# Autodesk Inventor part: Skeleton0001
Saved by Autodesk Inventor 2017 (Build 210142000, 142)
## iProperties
Created: 2020-09
Part Number: Skeleton0001
Material: Generic
Document SubType Name: Modeling
Designer: X
Density: 1 g/cm^3
Appearance: Default
_SkeletonDoc: Frame Skeleton File
_Version: 15.0.0
Author: X
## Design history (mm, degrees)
sketch "Szkielet odniesienia"
